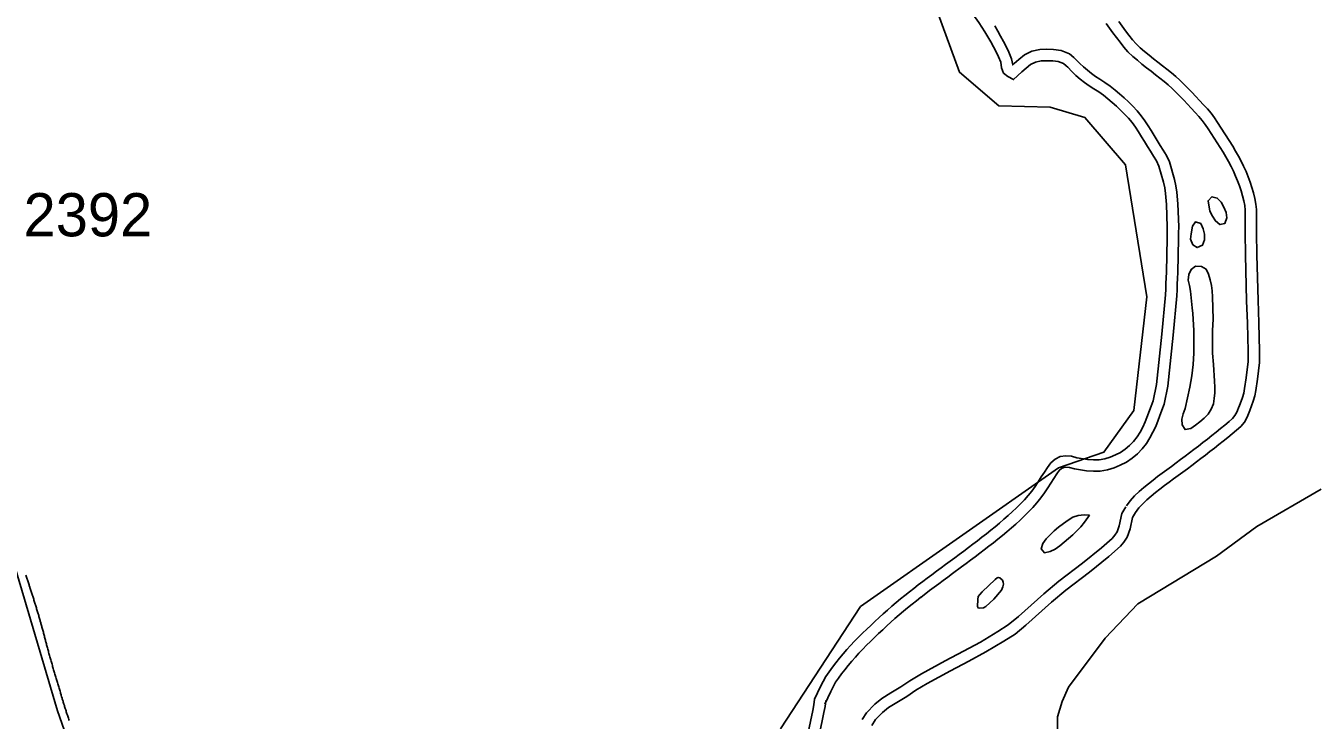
# Model space of a CAD drawing. Extents: x 1364363 to 1407445, y 538563 to 573342.
# Drawn here: x 1376165 to 1379893, y 560578 to 562586 of the extents above; entities that cross this region are included whole.
import ezdxf

# ---------------------------------------------------------------- set-up
doc = ezdxf.new("R2010")
doc.units = 0
for name, color, linetype in [('Exist Boundary Political City Limit New', 7, 'Continuous'), ('Exist Hydrographic Buffer Line', 7, 'Continuous'), ('Exist Hydrographic Creek Double Shore', 7, 'Continuous'), ('Exist Hydrographic Island Shore', 7, 'Continuous'), ('Exist Railroad Mainline', 7, 'Continuous'), ('Exist Road Secondary Type 51 Attributed', 7, 'Continuous'), ('Exist Road Secondary Type 51 Number Label', 7, 'Continuous')]:
    doc.layers.add(name, color=color, linetype=linetype)

msp = doc.modelspace()

# ---------------------------------------------------------------- linework, layer by layer
at = {"layer": 'Exist Boundary Political City Limit New'}
for points in [[(1378788.9, 562657.2), (1378864.8, 562451.4), (1378978.6, 562354.3), (1379127, 562350.9), (1379227, 562320.8), (1379344.4, 562183.6), (1379406.4, 561801.9), (1379368.5, 561473.9), (1379282.2, 561353.4), (1379151.1, 561308.1), (1378578.4, 560906.4), (1378347.2, 560553.2)], [(1376374.4, 560270.1), (1376256.2, 560605.1), (1376095, 561149.6), (1375994.4, 561314.9), (1375861.4, 561440), (1375696.1, 561585.2), (1375506.8, 561673.9), (1375261, 561746.6), (1375188.5, 561754.6), (1375206.1, 561788.9)]]:
    msp.add_lwpolyline(points, dxfattribs=at)
at = {"layer": 'Exist Hydrographic Buffer Line'}
for points in [[(1379288.9, 562592.2), (1379298.4, 562578.9), (1379308.2, 562565.4), (1379318.2, 562551.8), (1379328.5, 562538.3), (1379339.3, 562524.6), (1379351.6, 562510.6), (1379365.2, 562497.6), (1379378.6, 562486.2), (1379391.7, 562475.4), (1379404.8, 562464.8), (1379418.2, 562454.4), (1379431.4, 562444.4), (1379444.1, 562434.7), (1379456.2, 562425), (1379467.7, 562415.1), (1379479, 562404.7), (1379490.3, 562393.7), (1379501.5, 562382.5), (1379512.6, 562370.9), (1379523.8, 562359.2), (1379534.7, 562347.4), (1379545.7, 562335.5), (1379556.4, 562323.8), (1379566.1, 562312.4), (1379574.9, 562300.8), (1379583.4, 562288.3), (1379626.7, 562220.5), (1379634.3, 562207.1), (1379642, 562193.1), (1379649.5, 562179.1), (1379656.4, 562165.3), (1379662.8, 562151.5), (1379668.5, 562137.6), (1379673.9, 562123.3), (1379678.6, 562108.7), (1379682.9, 562094), (1379686.6, 562079.9), (1379689, 562066.5), (1379690, 562052.6), (1379690.4, 562037.4), (1379690.5, 562021.4), (1379690.5, 562005.3), (1379690.3, 561988.6), (1379691.3, 561922.4), (1379694.7, 561791.1), (1379697.5, 561725.9), (1379699.3, 561644.8), (1379699.3, 561629.4), (1379698.8, 561614.8), (1379693.4, 561568.1), (1379688.7, 561536.7), (1379686.6, 561523.5), (1379682.4, 561510.9), (1379673, 561485)], [(1378966.1, 562585.5), (1378974.9, 562570.7), (1378983.3, 562555.9), (1378991.5, 562540.9), (1378999.5, 562525.6), (1379007.3, 562509.5), (1379015.2, 562490.2), (1379018.2, 562472.8), (1379018.3, 562472.8), (1379022.9, 562477), (1379036, 562488.8), (1379052.4, 562501.8), (1379073.8, 562512.2), (1379096.7, 562516.9), (1379116.9, 562517.9), (1379136.1, 562517.2), (1379158, 562514.8), (1379182.5, 562505.1), (1379194.8, 562494.4)], [(1379194.8, 562494.5), (1379200.2, 562489.7), (1379212.2, 562477.2), (1379222.8, 562466.9), (1379234.1, 562457.3), (1379246, 562447.8), (1379257.8, 562439.1), (1379270.3, 562431.2), (1379285.1, 562422.4), (1379300.5, 562411.6), (1379314.5, 562400.2), (1379327.4, 562389), (1379340.2, 562377.6), (1379352.7, 562365.9), (1379365.2, 562353.9), (1379377.8, 562340.5), (1379389.7, 562326), (1379400.2, 562311.2), (1379409.6, 562297), (1379418.7, 562282.8), (1379427.6, 562268.6), (1379436.3, 562254.4), (1379444.9, 562240.2), (1379453.4, 562226.1), (1379462.6, 562210.9), (1379471.8, 562192.2), (1379485.7, 562141.7), (1379490.2, 562123.4), (1379492.5, 562104.9), (1379495.7, 562071.5), (1379498.2, 562004.9), (1379497.9, 561987.7), (1379497.7, 561971.2), (1379497.4, 561954.7), (1379497.1, 561938.2), (1379496.7, 561921.7), (1379496.3, 561905.3), (1379495.9, 561888.7), (1379495.4, 561872.1), (1379494.7, 561855.7), (1379494.2, 561839.2), (1379493.6, 561822.7), (1379492.8, 561805.3), (1379482, 561691.1), (1379466.5, 561544.1), (1379456.3, 561492.2), (1379449.6, 561474.3), (1379431.8, 561427.5), (1379423.8, 561410.6), (1379415.1, 561394.3), (1379404.7, 561378), (1379392.3, 561362.5), (1379378.6, 561348.4), (1379363.7, 561335.7), (1379347.1, 561324.3), (1379329.4, 561315.1), (1379311.4, 561307.6), (1379291.9, 561301.7), (1379271.4, 561298.5), (1379251.6, 561297.9), (1379231.8, 561298.8), (1379196.5, 561304.9), (1379182.1, 561309), (1379172.2, 561309.8), (1379165.8, 561309), (1379159.8, 561305.6), (1379152.5, 561299.6), (1379145.7, 561290.2), (1379137.1, 561277.3), (1379128.4, 561263.7), (1379119.4, 561249.6), (1379109.8, 561235.2), (1379099.5, 561220.7), (1379088.3, 561206.6), (1379076.4, 561193.1), (1379064.2, 561180.5), (1379051.8, 561168.3), (1379039.4, 561156.7), (1379026.9, 561145.3), (1379014.3, 561134.1), (1379001.5, 561123.1), (1378988.6, 561112.3), (1378975.6, 561101.7), (1378962.5, 561091.3), (1378949.4, 561081), (1378936.2, 561070.8), (1378923, 561060.8), (1378909.8, 561050.8), (1378896.5, 561040.9), (1378883.3, 561031.1), (1378870.1, 561021.3), (1378843.7, 561001.8), (1378830.6, 560992), (1378817.3, 560982.2), (1378804.2, 560972.5), (1378778.1, 560953), (1378752.2, 560933.2)], [(1379347, 561197.5), (1379357.7, 561212.4), (1379370.8, 561226.8), (1379384.2, 561239.3), (1379397.3, 561250.7), (1379410.6, 561261.7), (1379424, 561272.3), (1379437.3, 561282.4), (1379450.7, 561292.5), (1379477.3, 561312.1), (1379490.5, 561321.8), (1379503.6, 561331.5), (1379516.6, 561341.2), (1379529.5, 561350.9), (1379542.4, 561360.8), (1379555.3, 561370.7), (1379568.2, 561380.8), (1379581.1, 561390.8), (1379593.9, 561400.8), (1379606.7, 561411), (1379619.2, 561421.1), (1379631.6, 561431.3), (1379643.8, 561441.3), (1379653.8, 561450.3), (1379660.8, 561458.7), (1379666.3, 561468.5), (1379673.5, 561486.3)], [(1379345.2, 561194.8), (1379334.2, 561175.9), (1379326.2, 561140.1), (1379320, 561122.7), (1379313.1, 561112.9), (1379305.8, 561103.6), (1379275.2, 561076.7), (1379219.9, 561031.8), (1379151.2, 560980), (1379108.5, 560943.7), (1379034.9, 560877.9), (1379005.6, 560853.5), (1378975.3, 560834.3), (1378924.7, 560804.1), (1378875.8, 560777.5), (1378823.1, 560749.3), (1378754.5, 560712.4), (1378720.6, 560692.3), (1378694.4, 560674.7), (1378665.6, 560657.5), (1378639.8, 560640.9), (1378619.4, 560624.5), (1378595.4, 560599.8), (1378583.3, 560580)], [(1378752.5, 560933.4), (1378739.7, 560923.4), (1378727.1, 560913.3), (1378714.5, 560903.2), (1378702.2, 560892.9), (1378690, 560882.5), (1378677.8, 560872), (1378665.8, 560861.4), (1378654, 560850.6), (1378642.3, 560839.7), (1378630.6, 560828.6), (1378619, 560817.3), (1378607.3, 560805.9), (1378595.8, 560794.6), (1378584.5, 560783.3), (1378573.8, 560772.1), (1378563.5, 560760.6), (1378553.1, 560748.4), (1378542.6, 560736), (1378532.4, 560723.8), (1378522.9, 560711.7), (1378514.1, 560699.7), (1378506.3, 560687.7), (1378499.2, 560675), (1378492.3, 560661.2), (1378474.8, 560624.6)], [(1378477.8, 560634.8), (1378475.7, 560617.5), (1378472.5, 560599.9), (1378458.2, 560533.8)]]:
    msp.add_lwpolyline(points, dxfattribs=at)
at = {"layer": 'Exist Hydrographic Creek Double Shore'}
for points in [[(1378689.4, 563032.9), (1378751.7, 562874.1), (1378756.2, 562858.2), (1378761.5, 562842.8), (1378794.5, 562767.8), (1378802.1, 562753.3), (1378810.5, 562739.2), (1378819.6, 562725.5), (1378829.3, 562712.2), (1378839.1, 562699.1), (1378849.2, 562686.1), (1378859.4, 562673.3), (1378869.7, 562660.5), (1378880, 562647.7), (1378890.3, 562634.9), (1378900.4, 562622), (1378910.4, 562608.9), (1378920, 562595.7), (1378929.3, 562582.1), (1378937.9, 562568.7)], [(1379325.1, 562598.1), (1379334.7, 562584.7), (1379344.5, 562571.5), (1379354.4, 562558.4), (1379364.6, 562545.6), (1379375.3, 562533.3), (1379387.2, 562522), (1379399.7, 562511.3), (1379412.4, 562500.8), (1379425.1, 562490.5), (1379438.2, 562480.5), (1379451.3, 562470.5), (1379464.3, 562460.5), (1379477.1, 562450.3), (1379489.5, 562439.6), (1379501.5, 562428.5), (1379513.3, 562417.1), (1379524.9, 562405.4), (1379536.3, 562393.6), (1379547.7, 562381.7), (1379558.8, 562369.7), (1379569.9, 562357.6), (1379581, 562345.5), (1379591.6, 562333), (1379601.6, 562319.9), (1379610.8, 562306.3), (1379654.8, 562237.4), (1379662.9, 562223.1), (1379670.8, 562208.7), (1379678.6, 562194.2), (1379686, 562179.6), (1379692.8, 562164.7), (1379699.1, 562149.6), (1379704.8, 562134.1), (1379710, 562118.5), (1379714.6, 562102.7), (1379718.7, 562086.8), (1379721.5, 562070.6), (1379722.8, 562054.3), (1379723.2, 562037.9), (1379723.3, 562021.5), (1379723.3, 562005.1), (1379723.1, 561988.7), (1379724.1, 561923), (1379727.5, 561792.2), (1379730.3, 561727), (1379732.1, 561645.2), (1379732.1, 561628.8), (1379731.5, 561612.3), (1379726, 561563.8), (1379721.1, 561531.6), (1379718.6, 561515.7), (1379713.3, 561500.1), (1379703.9, 561473.9)], [(1378937.9, 562568.7), (1378946.6, 562554.2), (1378954.7, 562539.9), (1378962.5, 562525.5), (1378970.1, 562510.9), (1378977.3, 562496.1), (1378983.5, 562481), (1378986.3, 562464.8), (1378991.5, 562449.3), (1379004.6, 562439.6), (1379020.6, 562430.4), (1379045, 562452.7), (1379057.2, 562463.7), (1379070, 562473.9), (1379084.5, 562480.9), (1379100.9, 562484.2), (1379117.2, 562485), (1379133.8, 562484.4), (1379150.1, 562482.7), (1379165.2, 562476.7), (1379173.2, 562469.7)], [(1379173.2, 562469.7), (1379177.5, 562466), (1379188.9, 562454.1), (1379200.7, 562442.6), (1379213.2, 562432), (1379226, 562421.8), (1379239.3, 562412), (1379253.1, 562403.2), (1379267.3, 562394.8), (1379280.7, 562385.4), (1379293.4, 562375), (1379305.8, 562364.4), (1379318.1, 562353.4), (1379330.1, 562342.2), (1379341.9, 562330.8), (1379353.2, 562318.8), (1379363.6, 562306.1), (1379373.1, 562292.7), (1379382.1, 562279.1), (1379391, 562265.2), (1379399.7, 562251.3), (1379408.3, 562237.3), (1379416.8, 562223.3), (1379425.2, 562209.2), (1379433.8, 562195.1), (1379441, 562180.4), (1379454, 562133.4), (1379457.9, 562117.4), (1379459.9, 562101.2), (1379463, 562069.3), (1379465.3, 562004.5), (1379465.1, 561988.1), (1379464.9, 561971.7), (1379464.6, 561955.3), (1379464.3, 561938.9), (1379463.9, 561922.5), (1379463.5, 561906.1), (1379463.1, 561889.6), (1379462.6, 561873.2), (1379462, 561856.8), (1379461.4, 561840.4), (1379460.8, 561824), (1379460.1, 561807.6), (1379449.3, 561694.4), (1379434.1, 561549), (1379424.6, 561501.2), (1379418.9, 561485.9), (1379401.6, 561440.3), (1379394.5, 561425.4), (1379386.7, 561410.9), (1379378, 561397.1), (1379367.7, 561384.3), (1379356.1, 561372.4), (1379343.6, 561361.7), (1379330.2, 561352.5), (1379315.5, 561344.9), (1379300.3, 561338.5), (1379284.6, 561333.8), (1379268.3, 561331.3), (1379251.9, 561330.7), (1379235.4, 561331.5), (1379203.8, 561336.9), (1379188, 561341.5), (1379171.5, 561342.7), (1379155.4, 561340.8), (1379141, 561332.7), (1379128.3, 561322.1), (1379118.8, 561308.9), (1379109.7, 561295.3), (1379100.8, 561281.4), (1379091.9, 561267.5), (1379082.8, 561253.8), (1379073.3, 561240.5), (1379063.1, 561227.7), (1379052.3, 561215.4), (1379040.9, 561203.6), (1379029.1, 561192), (1379017.1, 561180.8), (1379005, 561169.7), (1378992.7, 561158.9), (1378980.3, 561148.1), (1378967.7, 561137.6), (1378955, 561127.2), (1378942.1, 561117), (1378929.2, 561106.9), (1378916.2, 561096.9), (1378903.2, 561086.9), (1378890.1, 561077), (1378876.9, 561067.2), (1378863.7, 561057.4), (1378850.6, 561047.6), (1378837.4, 561037.9), (1378824.1, 561028.1), (1378811, 561018.3), (1378797.8, 561008.6), (1378784.6, 560998.8), (1378771.4, 560989), (1378758.3, 560979.1), (1378745.3, 560969.2), (1378732.3, 560959.2)], [(1379373.6, 561178.3), (1379383.2, 561191.7), (1379394.2, 561203.7), (1379406.2, 561214.9), (1379418.6, 561225.7), (1379431.2, 561236.2), (1379444.1, 561246.4), (1379457.1, 561256.3), (1379470.3, 561266.2), (1379483.5, 561275.9), (1379496.7, 561285.7), (1379509.9, 561295.4), (1379523.2, 561305.1), (1379536.3, 561314.9), (1379549.4, 561324.8), (1379562.4, 561334.8), (1379575.3, 561344.8), (1379588.4, 561354.9), (1379601.3, 561364.9), (1379614.2, 561375.1), (1379627.1, 561385.3), (1379639.9, 561395.6), (1379652.5, 561406), (1379665.2, 561416.5), (1379677.5, 561427.4), (1379688, 561440.1), (1379695.9, 561454.3), (1379703.9, 561473.9)], [(1379373.6, 561178.3), (1379365.1, 561163.7), (1379357.8, 561131), (1379349.5, 561107.5), (1379339.4, 561093.2), (1379329.7, 561080.9), (1379296.4, 561051.7), (1379240.1, 561006), (1379171.7, 560954.4), (1379130.1, 560919), (1379056.4, 560853.1), (1379025, 560826.9), (1378992.5, 560806.3), (1378940.9, 560775.6), (1378891.4, 560748.6), (1378838.6, 560720.4), (1378770.6, 560683.8), (1378738.1, 560664.5), (1378712, 560647), (1378682.9, 560629.6), (1378659, 560614.3), (1378641.5, 560600.2), (1378621.4, 560579.6), (1378611.3, 560562.9)], [(1378732.3, 560959.2), (1378719.4, 560949.1), (1378706.5, 560938.9), (1378693.7, 560928.5), (1378681.1, 560918), (1378668.6, 560907.4), (1378656.2, 560896.6), (1378643.9, 560885.8), (1378631.8, 560874.8), (1378619.8, 560863.6), (1378607.9, 560852.3), (1378596.1, 560840.8), (1378584.3, 560829.4), (1378572.6, 560817.9), (1378561.1, 560806.3), (1378549.7, 560794.4), (1378538.8, 560782.2), (1378528.1, 560769.7), (1378517.5, 560757.1), (1378506.9, 560744.4), (1378496.8, 560731.5), (1378487.1, 560718.3), (1378478.2, 560704.7), (1378470.2, 560690.4), (1378462.8, 560675.7), (1378445.2, 560638.7)], [(1378445.2, 560638.7), (1378443.3, 560622.4), (1378440.3, 560606.3), (1378426.5, 560542.5)]]:
    msp.add_lwpolyline(points, dxfattribs=at)
at = {"layer": 'Exist Hydrographic Island Shore'}
for points in [[(1379588.5, 562050.2), (1379595.6, 562035.3), (1379604.2, 562021.5), (1379617.6, 562011.3), (1379632, 562014.6), (1379637.5, 562030.3), (1379635.4, 562046.5), (1379628.9, 562061.8), (1379621.1, 562076.3), (1379609.8, 562087.8), (1379594.2, 562091.8), (1379583, 562080.2), (1379588.5, 562050.2)], [(1379534.5, 561984.8), (1379532.1, 561968.5), (1379539.1, 561952.9), (1379551.4, 561944.7), (1379567.3, 561951.2), (1379572.4, 561966.6), (1379572.6, 561983.1), (1379568.6, 561999.3), (1379562, 562014.3), (1379546.8, 562019.2), (1379538.4, 562006.9), (1379534.5, 561984.8)], [(1379516.7, 561479.6), (1379511.4, 561464), (1379506.9, 561448.3), (1379507.9, 561431.9), (1379516.8, 561418.5), (1379532.9, 561421.4), (1379546.3, 561430.7), (1379559.3, 561440.9), (1379571.7, 561451.8), (1379583.3, 561463.3), (1379592.1, 561477.3), (1379598.5, 561492.4), (1379601.1, 561508.7), (1379602.6, 561525), (1379602.9, 561541.4), (1379602.1, 561557.9), (1379599, 561606.7), (1379595.6, 561639.2), (1379596.3, 561704.6), (1379597.3, 561721), (1379598.1, 561737.5), (1379595.9, 561802.6), (1379595.2, 561819.1), (1379592.9, 561835.3), (1379588.8, 561851.5), (1379583.9, 561867.7), (1379577.3, 561882.3), (1379564, 561890.4), (1379547.2, 561891), (1379534.7, 561881.6), (1379527.1, 561866.6), (1379525.6, 561850.8), (1379529.6, 561834.7), (1379532.4, 561818.4), (1379537.6, 561770.3), (1379539, 561753.9), (1379540.2, 561737.5), (1379541, 561721), (1379541.5, 561704.6), (1379541.7, 561688.2), (1379541.8, 561671.8), (1379541.8, 561655.3), (1379541.5, 561638.9), (1379540.7, 561622.5), (1379539.8, 561606.1), (1379538.3, 561589.9), (1379536.1, 561573.6), (1379533.4, 561557.5), (1379530.2, 561541.4), (1379516.7, 561479.6)], [(1379240.7, 561171.3), (1379224.4, 561172.1), (1379208, 561170.3), (1379192.5, 561165.1), (1379178.6, 561156.3), (1379165.2, 561146.9), (1379150.4, 561136.4), (1379138.1, 561125.4), (1379126.1, 561114.3), (1379115.2, 561102), (1379105.7, 561088.5), (1379100.9, 561073.3), (1379110.3, 561061.6), (1379126.1, 561066.3), (1379141.3, 561072.7), (1379154.3, 561082.5), (1379167.2, 561092.7), (1379179.8, 561103.3), (1379192.2, 561114.2), (1379204.1, 561125.3), (1379215.3, 561137.2), (1379225.4, 561150.2), (1379240.7, 561171.3)], [(1378930.4, 560948.9), (1378967.1, 560985.3), (1378972.9, 560990.1), (1378976.5, 560990.9), (1378980.6, 560989.9), (1378989.1, 560982.6), (1378991, 560977.6), (1378991.3, 560971.1), (1378990, 560964), (1378985.5, 560954.3), (1378963.4, 560928.2), (1378940.5, 560906.4), (1378933.5, 560902.7), (1378922.1, 560902.1), (1378917.9, 560902.9), (1378916.1, 560906.7), (1378917, 560926.8), (1378918.6, 560935.3), (1378923.3, 560941.4), (1378930.4, 560948.9)]]:
    msp.add_lwpolyline(points, dxfattribs=at)
at = {"layer": 'Exist Railroad Mainline'}
for points in [[(1376164.5, 560997.3), (1376165.3, 560994.6), (1376166.4, 560991.7), (1376167.4, 560989), (1376168.2, 560986.3), (1376169.2, 560983.5), (1376170.3, 560980.7), (1376171.2, 560978), (1376172.1, 560975.2), (1376173, 560972.4), (1376174, 560969.6), (1376174.9, 560966.9), (1376175.9, 560964.1), (1376176.7, 560961.3), (1376177.6, 560958.6), (1376178.7, 560955.8), (1376179.5, 560953), (1376180.4, 560950.2), (1376181.2, 560947.5), (1376182.2, 560944.6), (1376183.2, 560941.9), (1376184, 560939), (1376184.9, 560936.3), (1376185.7, 560933.5), (1376186.7, 560930.7), (1376187.5, 560927.9), (1376188.4, 560925.1), (1376189.2, 560922.4), (1376190.1, 560919.6), (1376191, 560916.7), (1376191.9, 560914), (1376192.7, 560911.2), (1376193.6, 560908.4), (1376194.5, 560905.6), (1376195.3, 560902.8), (1376196.1, 560900), (1376197, 560897.2), (1376197.8, 560894.4), (1376198.7, 560891.6), (1376199.5, 560888.8), (1376200.4, 560886), (1376201.1, 560883.2), (1376202, 560880.4), (1376202.8, 560877.6), (1376203.7, 560874.8), (1376204.4, 560871.9), (1376205.2, 560869.1), (1376206, 560866.3), (1376206.7, 560863.5), (1376207.7, 560860.7), (1376208.4, 560857.9), (1376209.1, 560855.1), (1376210, 560852.3), (1376210.7, 560849.4), (1376211.5, 560846.6), (1376212.3, 560843.8), (1376213.1, 560841), (1376213.8, 560838.1), (1376214.6, 560835.3), (1376215.4, 560832.5), (1376216.1, 560829.7), (1376216.9, 560826.9), (1376217.6, 560824), (1376218.3, 560821.2), (1376219.2, 560818.4), (1376219.9, 560815.6), (1376220.6, 560812.7), (1376221.4, 560809.9), (1376222, 560807), (1376222.7, 560804.2), (1376223.5, 560801.4), (1376224.3, 560798.6), (1376224.9, 560795.7), (1376225.6, 560792.9), (1376226.3, 560790.1)], [(1376226.3, 560790.1), (1376227.3, 560786.9), (1376228.1, 560783.8), (1376229, 560780.6), (1376229.9, 560777.5), (1376230.7, 560774.3), (1376231.7, 560771.2), (1376232.5, 560768.1), (1376233.4, 560764.9), (1376234.2, 560761.7), (1376235.1, 560758.6), (1376236, 560755.5), (1376237, 560752.3), (1376237.9, 560749.2), (1376238.7, 560746), (1376239.7, 560743), (1376240.5, 560739.8), (1376241.5, 560736.6), (1376242.3, 560733.5), (1376243.2, 560730.4), (1376244.2, 560727.2), (1376245.1, 560724.1), (1376246, 560721), (1376246.8, 560717.9), (1376247.8, 560714.7), (1376248.8, 560711.5), (1376249.6, 560708.5), (1376250.6, 560705.3), (1376251.5, 560702.2), (1376252.4, 560699.1), (1376253.4, 560696), (1376254.2, 560692.8), (1376255.2, 560689.7), (1376256.2, 560686.6), (1376257, 560683.4), (1376258, 560680.3), (1376258.8, 560677.2), (1376259.9, 560674.1), (1376260.8, 560670.9), (1376261.7, 560667.8), (1376262.7, 560664.7), (1376263.7, 560661.6), (1376264.6, 560658.4), (1376265.5, 560655.3), (1376266.5, 560652.2), (1376267.3, 560649), (1376268.4, 560645.9), (1376269.4, 560642.8), (1376270.2, 560639.7), (1376271.2, 560636.5), (1376272.3, 560633.4), (1376273.1, 560630.3), (1376274.1, 560627.2), (1376275.1, 560624.1), (1376276.2, 560621), (1376277, 560617.9), (1376278, 560614.8), (1376279, 560611.6), (1376280, 560608.5), (1376281, 560605.4), (1376281.9, 560602.3), (1376282.8, 560599.2), (1376283.8, 560596), (1376284.9, 560592.9), (1376285.9, 560589.9), (1376286.9, 560586.8), (1376287.8, 560583.6), (1376288.9, 560580.5), (1376289.9, 560577.4)]]:
    msp.add_lwpolyline(points, dxfattribs=at)
at = {"layer": 'Exist Road Secondary Type 51 Attributed'}
msp.add_lwpolyline([(1379909.7, 561246.3), (1379724.6, 561138.1), (1379607.9, 561051.9), (1379380.3, 560914.3), (1379285.6, 560815.2), (1379179.7, 560673.1), (1379161.7, 560632.5), (1379148.1, 560587.5), (1379148.1, 560549.1), (1379154.3, 560517.7), (1379222.5, 560402.6), (1379281.1, 560358.9), (1379386.6, 560311.2), (1379487.2, 560275.5), (1379646, 560224), (1379761.5, 560184.8), (1379936.1, 560109.5)], dxfattribs=at)

# ---------------------------------------------------------------- texts
at = {"layer": 'Exist Road Secondary Type 51 Number Label'}
msp.add_text('2392', height=125, dxfattribs=at).set_placement((1376158.3, 561977.1))

doc.saveas('drawing.dxf')
